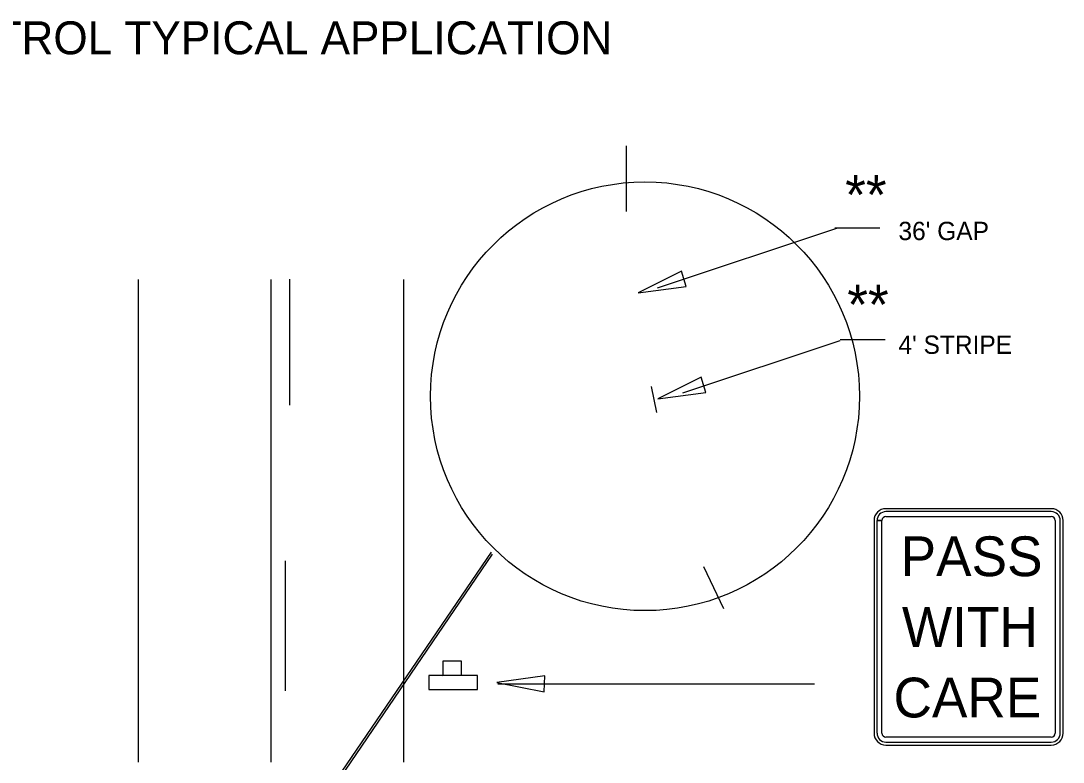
# Model space of a CAD drawing. Extents: x 612.5 to 619.9, y 611 to 621.2.
# Drawn here: x 616.149 to 619.562, y 618.768 to 621.195 of the extents above; entities that cross this region are included whole.
import ezdxf

# ---------------------------------------------------------------- set-up
doc = ezdxf.new("R2010")
doc.units = 0
for name, color, linetype in [('DETL-DIMS', 7, 'Continuous'), ('DETL-LINE', 7, 'Continuous'), ('DETL-NOTE', 7, 'Continuous'), ('DETL-TITL', 7, 'Continuous'), ('USER-BORD', 7, 'Continuous')]:
    doc.layers.add(name, color=color, linetype=linetype)

# ---------------------------------------------------------------- blocks, each defined once
blk = doc.blocks.new('SIGN13')
at = {"layer": 'USER-BORD'}
for points in [[(-0.0134, 0.0182), (0.011, 0.0189), (0.011, 0.0371), (-0.0134, 0.0371)], [(-0.0314, 0.0182), (-0.0314, 0), (0.032, 0), (0.032, 0.0182)]]:
    blk.add_lwpolyline(points, close=True, dxfattribs=at)

msp = doc.modelspace()

# ---------------------------------------------------------------- linework, layer by layer
at = {"layer": 'DETL-DIMS'}
for p, q in [((618.2332, 620.3206), (618.8237, 620.5176)), ((618.8139, 620.5176), (618.9618, 620.5176)), ((618.3165, 619.9772), (618.8315, 620.1488)), ((618.8315, 620.1514), (618.9794, 620.1514)), ((617.6885, 619.455), (617.0695, 618.5466)), ((617.7105, 619.0246), (618.7477, 619.0246))]:
    msp.add_line(p, q, dxfattribs=at)
for points in [[(618.3273, 620.3254), (618.3121, 620.3752), (618.1702, 620.3048)], [(618.3922, 619.9786), (618.377, 620.0285), (618.235, 619.958)], [(617.8628, 618.9984), (617.8642, 619.0505), (617.7072, 619.0286)]]:
    msp.add_lwpolyline(points, close=True, dxfattribs=at)
msp.add_circle((618.1926, 619.966), 0.7021, dxfattribs=at)
at = {"layer": 'DETL-LINE'}
for p, q in [((618.131, 620.7858), (618.131, 620.5714)), ((617.0282, 620.3498), (617.0282, 619.9368)), ((616.5334, 620.3482), (616.5334, 618.7678)), ((616.9677, 620.3482), (616.9677, 618.7678)), ((617.4019, 620.3482), (617.4019, 618.7678)), ((618.2133, 619.9981), (618.2303, 619.9132)), ((619.5229, 619.5978), (618.9811, 619.5978)), ((619.5229, 619.5882), (618.9811, 619.5882)), ((618.9811, 619.572), (619.5229, 619.572)), ((618.9425, 619.5591), (618.9425, 618.8626)), ((618.9683, 619.5591), (618.9521, 619.5591)), ((618.9521, 619.5591), (618.9521, 618.8626)), ((618.9521, 619.5591), (618.9683, 619.5591)), ((618.9683, 618.8626), (618.9683, 619.5591)), ((619.5358, 619.5591), (619.5358, 618.8626)), ((619.5519, 618.8626), (619.5519, 619.5591)), ((619.5616, 618.8626), (619.5616, 619.5591)), ((617.0145, 619.4275), (617.0145, 619.0008)), ((617.6924, 619.4492), (617.0734, 618.5406)), ((618.3841, 619.409), (618.4495, 619.271)), ((619.5229, 618.8497), (618.9811, 618.8497)), ((618.9811, 618.8336), (619.5229, 618.8336)), ((618.9811, 618.8239), (619.5229, 618.8239))]:
    msp.add_line(p, q, dxfattribs=at)
for centre, radius, start, end in [((618.9812, 619.5591), 0.0387, 90, 180), ((618.9812, 619.5591), 0.029, 90, 180), ((618.9812, 619.5591), 0.0129, 90, 180), ((619.5229, 619.5591), 0.0387, 0, 90), ((619.5229, 619.5591), 0.029, 0, 90), ((619.5229, 619.5591), 0.0129, 0, 90), ((618.9812, 618.8626), 0.0387, 180, 270), ((618.9812, 618.8626), 0.029, 180, 270), ((618.9812, 618.8626), 0.0129, 180, 270), ((619.5229, 618.8626), 0.0387, 270, 0), ((619.5229, 618.8626), 0.029, 270, 0), ((619.5229, 618.8626), 0.0129, 270, 0)]:
    msp.add_arc(centre, radius, start, end, dxfattribs=at)

# ---------------------------------------------------------------- block references
at = {"layer": 'DETL-LINE', "xscale": 2.5084471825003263, "yscale": 2.508447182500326, "rotation": -0.14210881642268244}
msp.add_blockref('SIGN13', (617.5639, 619.0056), dxfattribs=at)

# ---------------------------------------------------------------- texts
at = {"layer": 'DETL-LINE'}
for s, p in [('PASS', (619.0294, 619.3769)), ('WITH', (619.0339, 619.1451)), ('CARE', (619.0062, 618.9142))]:
    msp.add_text(s, height=0.13026, dxfattribs=at).set_placement(p)
at = {"layer": 'DETL-NOTE'}
for s, height, p in [('**', 0.13026, (618.848, 620.5607)), ("36' GAP", 0.06, (619.0224, 620.4774)), ('**', 0.13026, (618.8548, 620.2011)), ("4' STRIPE", 0.06, (619.0224, 620.1049))]:
    msp.add_text(s, height=height, dxfattribs=at).set_placement(p)
at = {"layer": 'DETL-TITL'}
msp.add_text('TEMPORARY TRAFFIC CONTROL TYPICAL APPLICATION', height=0.108, dxfattribs=at).set_placement((614.1375, 621.0859))

doc.saveas('drawing.dxf')
